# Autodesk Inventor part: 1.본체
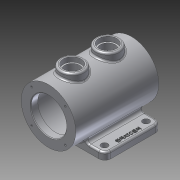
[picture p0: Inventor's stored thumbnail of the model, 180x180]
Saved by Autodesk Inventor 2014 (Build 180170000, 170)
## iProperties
Created: 2014-12
Part Number: 1.본체
Material: 알루미늄 6061
Document SubType Name: Modeling
Designer: Owner
Mass: 1293.9 g
Surface Area: 1040.15 cm^2
Volume: 477.456 cm^3
Density: 2.71 g/cm^3
Appearance: 알루미늄 - 평지
Author: Owner
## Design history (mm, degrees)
sketch "스케치1"
  geometry: C1 r 46 at (0, 0); 1 further point
  constraints: 1 centre point, 1 coincident
  dimensions: "d0" = 92 diameter of C1
extrude "돌출1" new body sketch "스케치1" stored distance "d1" = 140; taper "d2" = 0 deg
node "작업 평면1"
sketch "스케치2"
  geometry: L1 (65, 40)-(-65, 40); L2 (-65, 40)-(-65, -55); L3 (-65, -55)-(65, -55); L4 (65, -55)-(65, 40); L5 (-46, -70)-(46, -70) reference; 2 further points
  constraints: 8 end point, 2 parallel, 1 horizontal, 1 midpoint, 1 perpendicular, 1 vertical alignment
  dimensions: "d4" = 15 distance between parallel lines of L5 L3; "d5" = 95 distance of L1.end L2.end; "d6" = 130 distance of L2.end L3.end
extrude "돌출2" join sketch "스케치2" distance "d7" = 12; taper "d8" = 0 deg
node "작업 평면2"
sketch "스케치3"
  geometry: L1 (-46, -70)-(46, -70) reference; C1 r 20 at (0, -30); C2 r 20 at (0, 30); 1 further point
  constraints: 2 centre point, 2 vertical alignment, 1 equal radius
  dimensions: "d10" = 40 diameter of C1; "d11" = 40 distance from line of C1.centre L1; "d12" = 60 distance of C2.centre C1.centre
extrude "돌출3" join sketch "스케치3" stored distance "d13" = 12; taper "d14" = 0 deg
sketch "스케치4"
  geometry: C1 r 46 at (0, 0) reference; C2 r 30 at (0, 0)
  constraints: 1 centre point, 1 coincident
  dimensions: "d15" = 60 diameter of C2
extrude "돌출4" cut sketch "스케치4" distance "d16" = 12; taper "d17" = 0 deg
sketch "스케치5"
  geometry: C1 r 30 at (0, 0) reference; C2 r 37.5 at (0, 0)
  constraints: 1 centre point, 1 coincident
  dimensions: "d18" = 75 diameter of C2
extrude "돌출5" cut sketch "스케치5" distance "d19" = 116; taper "d20" = 0 deg
hole "구멍1" diameter "d23" = 60; stored, may be unused: countersink angle "d27" = 90 deg, drill point angle "d29" = 0 deg; dims "d21" = 10, "d22" = 10, "d24" = 6, "d25" = 30, "d26" = 8, "d28" = 12
sketch "스케치6"
  geometry: L1 (0, 0)-(28.284, -28.284); L2 (0, 0)-(40, 0); C1 r 46 at (0, 0) reference; 1 further point
  constraints: 4 end point, 1 coincident, 1 equal length, 1 horizontal
  dimensions: "d30" = 40 distance of L1.start L1.end; "d31" = 45 deg angle of L1 L2
hole "구멍2" sketch "스케치6" at (28.284, -28.284) diameter "d32" = 3.242; stored, may be unused: countersink angle "d36" = 90 deg, drill point angle "d38" = 118 deg; dims "d33" = 8, "d34" = 30, "d35" = 8, "d37" = 10
hole "구멍3" diameter "d44" = 25; stored, may be unused: countersink angle "d48" = 90 deg, drill point angle "d50" = 0 deg; dims "d42" = 10, "d43" = 10, "d45" = 8, "d46" = 30, "d47" = 8, "d49" = 10
hole "구멍4" diameter "d53" = 25; stored, may be unused: countersink angle "d57" = 90 deg, drill point angle "d59" = 0 deg; dims "d51" = 10, "d52" = 10, "d54" = 8, "d55" = 30, "d56" = 8, "d58" = 10
fillet "모깎기1" dims "d60" = 5
sketch "스케치7"
  geometry: L1 (65, -55)-(65, 40) reference; L2 (65, 40)-(38.884, 40) reference; C1 r 5.5 at (52, 27.5); 1 further point
  constraints: 1 centre point
  dimensions: "d61" = 11 diameter of C1; "d62" = 13 distance from line of L1 C1.centre; "d63" = 12.5 distance from line of L2 C1.centre
extrude "돌출6" cut sketch "스케치7" stored distance "d64" = 116; taper "d65" = 0 deg
sketch "스케치8"
  geometry: L1 (-65, 40)-(-65, -55) reference; C1 r 5.5 at (-52, 27.5) reference; 2 further points
  constraints: 1 other
  dimensions: "d72" = 35 vertical distance of point (-57, -7.5) C1.centre; "d73" = 8 distance from line of L1 point (-57, -7.5)
feature "엠보싱1" sketch "스케치8" dims "d74" = 1, "d75" = 0
fillet "모깎기2" dims "d76" = 10
fillet "모깎기3" dims "d77" = 3
chamfer "모따기1" distance "d78" = 1; stored, may be unused: second distance "d79" = 2, angle "d80" = 45 deg
node "솔리드1"
pattern_circular "원형 패턴1" dims angle "d40" = 360 deg
mirror "대칭1"
pattern_linear "직사각형 패턴1" dims "d68" = 104
other parameters: "d9" = -106
